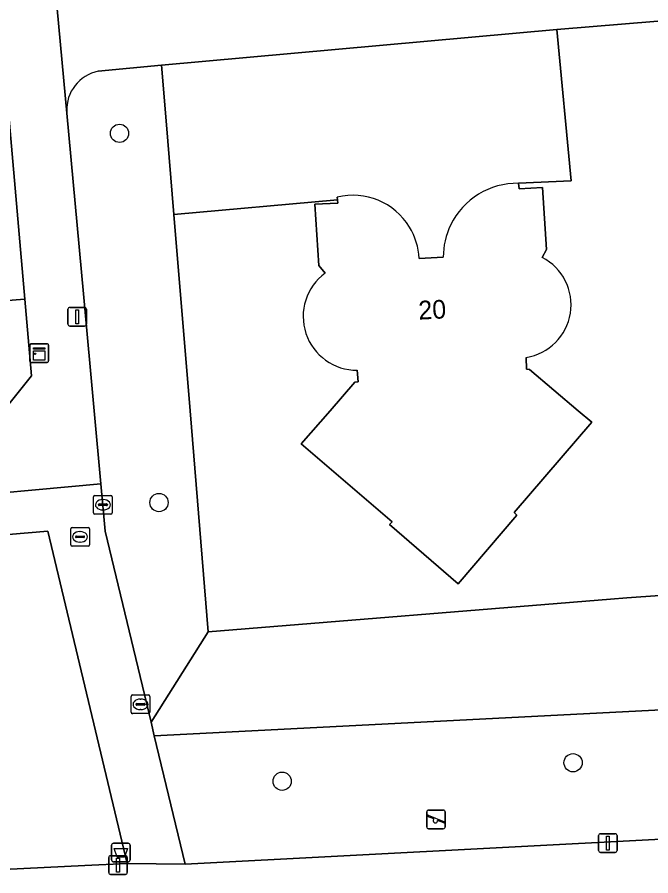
# Model space of a CAD drawing. Extents: x 160554 to 161248, y 385329 to 386506.
# Drawn here: x 161069.93 to 161103.88, y 385475.1 to 385521.08 of the extents above; entities that cross this region are included whole.
import ezdxf

# ---------------------------------------------------------------- set-up
doc = ezdxf.new("R2010")
doc.units = 0
for name, color, linetype in [('IMGEO_Afvalbak', 7, 'Continuous'), ('IMGEO_Boom', 7, 'Continuous'), ('IMGEO_Brandkraan', 7, 'Continuous'), ('IMGEO_Erf', 7, 'Continuous'), ('IMGEO_Groenvoorziening', 7, 'Continuous'), ('IMGEO_Hek', 7, 'Continuous'), ('IMGEO_Kast', 7, 'Continuous'), ('IMGEO_Kolk', 7, 'Continuous'), ('IMGEO_Lichtmast', 7, 'Continuous'), ('IMGEO_Pand', 7, 'Continuous'), ('IMGEO_Pand_nummerreeks', 7, 'Continuous'), ('IMGEO_Parkeervlak_open', 7, 'Continuous'), ('IMGEO_Rioolput', 7, 'Continuous'), ('IMGEO_Speelvoorziening', 7, 'Continuous'), ('IMGEO_Voetpad_open', 7, 'Continuous')]:
    doc.layers.add(name, color=color, linetype=linetype)

msp = doc.modelspace()

# ---------------------------------------------------------------- linework, layer by layer
at = {"layer": 'IMGEO_Afvalbak'}
for p, q in [((161075.09, 385476.846), (161075.88, 385476.846)), ((161075.88, 385476.846), (161075.09, 385476.846)), ((161074.99, 385475.946), (161074.99, 385476.746)), ((161074.99, 385476.746), (161074.99, 385475.946)), ((161075.98, 385476.746), (161075.98, 385475.946)), ((161075.98, 385475.946), (161075.98, 385476.746)), ((161075.88, 385475.846), (161075.09, 385475.846)), ((161075.09, 385475.846), (161075.88, 385475.846))]:
    msp.add_line(p, q, dxfattribs=at)
msp.add_lwpolyline([(161075.133, 385476.56), (161075.837, 385476.56), (161075.688, 385476.09), (161075.282, 385476.09), (161075.133, 385476.56)], dxfattribs=at)
for centre, start, end in [((161075.09, 385476.746), 90, 180), ((161075.09, 385476.746), 90, 180), ((161075.88, 385476.746), 0, 90), ((161075.88, 385476.746), 360, 90), ((161075.09, 385475.946), 180, 270), ((161075.09, 385475.946), 180, 270), ((161075.88, 385475.946), 270, 0), ((161075.88, 385475.946), 270, 0)]:
    msp.add_arc(centre, 0.1, start, end, dxfattribs=at)
at = {"layer": 'IMGEO_Boom'}
for centre in [(161075.416, 385514.863), (161077.531, 385495.089), (161099.716, 385481.154), (161084.129, 385480.164)]:
    msp.add_circle(centre, 0.489, dxfattribs=at)
at = {"layer": 'IMGEO_Brandkraan'}
for p, q in [((161072.802, 385492.826), (161072.802, 385493.678)), ((161072.877, 385493.752), (161073.729, 385493.752)), ((161073.29, 385493.532), (161073.315, 385493.532)), ((161073.803, 385493.678), (161073.803, 385492.826)), ((161073.061, 385493.246), (161073.061, 385493.258)), ((161073.499, 385493.209), (161073.101, 385493.209)), ((161073.104, 385493.295), (161073.502, 385493.295)), ((161073.313, 385492.972), (161073.288, 385492.972)), ((161073.545, 385493.258), (161073.545, 385493.246)), ((161073.729, 385492.752), (161072.877, 385492.752))]:
    msp.add_line(p, q, dxfattribs=at)
for points in [[(161072.802, 385492.826), (161072.802, 385493.678)], [(161072.877, 385493.752), (161073.729, 385493.752)], [(161073.803, 385493.678), (161073.803, 385492.826)], [(161073.729, 385492.752), (161072.877, 385492.752)]]:
    msp.add_lwpolyline(points, dxfattribs=at)
for centre, radius, start, end in [((161072.879, 385493.676), 0.0765, 91.552, 178.448), ((161072.879, 385493.676), 0.0765, 91.552, 178.448), ((161073.727, 385493.676), 0.0765, 1.552, 88.448), ((161073.727, 385493.676), 0.0765, 1.552, 88.448), ((161073.101, 385493.255), 0.0403, 85.8775, 175.7526), ((161073.098, 385493.245), 0.0366, 178.938, 274.7102), ((161073.502, 385493.252), 0.043, 264.8664, 352.4533), ((161073.506, 385493.257), 0.0386, 1.7309, 96.639), ((161072.879, 385492.828), 0.0765, 181.552, 268.448), ((161072.879, 385492.828), 0.0765, 181.552, 268.448), ((161073.727, 385492.828), 0.0765, 271.552, 358.448), ((161073.727, 385492.828), 0.0765, 271.552, 358.448)]:
    msp.add_arc(centre, radius, start, end, dxfattribs=at)
for centre, major_axis, ratio, start_param, end_param in [((161073.289, 385493.252), (-0.387, 0.002), 0.722429, 4.712389, 7.853982), ((161073.314, 385493.252), (-0.39, 0.002), 0.717154, 1.570796, 4.712389)]:
    msp.add_ellipse(centre, major_axis=major_axis, ratio=ratio, start_param=start_param, end_param=end_param, dxfattribs=at)
at = {"layer": 'IMGEO_Erf'}
for points in [[(161055.383, 385534.953), (161054.863, 385540.93), (161051.732, 385540.657), (161051.228, 385546.438), (161054.359, 385546.711), (161054.342, 385546.908), (161053.822, 385552.885), (161050.82, 385552.623), (161050.31, 385558.469), (161053.313, 385558.73), (161053.29, 385558.99), (161061.734, 385559.726), (161062.266, 385553.62), (161062.786, 385547.643), (161063.307, 385541.665), (161063.827, 385535.688), (161064.348, 385529.711), (161064.868, 385523.733), (161065.389, 385517.756), (161065.91, 385511.778), (161066.441, 385505.676), (161070.343, 385505.975), (161065.541, 385560.907)], [(161133.129, 385516.169), (161132.125, 385523.449), (161118.748, 385522.087), (161098.852, 385520.428), (161099.614, 385512.321), (161096.798, 385512.189), (161096.834, 385511.893), (161098.073, 385511.953), (161098.284, 385508.638), (161098.064, 385508.211)], [(161086.428, 385507.375), (161086.093, 385507.779), (161085.879, 385511.067), (161087.118, 385511.127), (161087.1, 385511.298), (161078.327, 385510.513), (161079.193, 385500), (161080.166, 385488.17), (161101.718, 385489.917), (161102.588, 385489.988), (161119.033, 385491.139)], [(161097.203, 385502.861), (161097.217, 385502.237), (161097.376, 385502.22), (161099.996, 385500), (161100.713, 385499.393), (161096.55, 385494.556), (161096.708, 385494.41), (161093.56, 385490.732), (161089.884, 385493.907), (161090.021, 385494.054), (161085.153, 385498.232), (161086.695, 385500), (161088.029, 385501.53), (161088.208, 385501.553), (161088.156, 385502.174)]]:
    msp.add_lwpolyline(points, dxfattribs=at)
for centre, radius, start, end in [((161096.753, 385505.678), 2.852, 279.0799, 62.6351), ((161088.135, 385505.054), 2.88, 126.3299, 270.4276)]:
    msp.add_arc(centre, radius, start, end, dxfattribs=at)
at = {"layer": 'IMGEO_Groenvoorziening'}
for points in [[(161077.669, 385518.505), (161074.274, 385518.185)], [(161077.913, 385515.539), (161077.669, 385518.505)], [(161072.592, 385516.029), (161072.598, 385515.941)], [(161072.598, 385515.941), (161073.484, 385506.275)], [(161078.327, 385510.513), (161077.913, 385515.539)], [(161080.166, 385488.17), (161079.193, 385500), (161078.327, 385510.513)], [(161073.484, 385506.275), (161074.057, 385500), (161074.414, 385496.088), (161074.646, 385493.548), (161077.103, 385483.331)], [(161077.103, 385483.331), (161080.166, 385488.17)]]:
    msp.add_lwpolyline(points, dxfattribs=at)
for points in [[(161065.454, 385495.276), (161069.208, 385500), (161070.701, 385501.878), (161070.343, 385505.975), (161066.441, 385505.676), (161057.997, 385504.94), (161051.262, 385504.235), (161048.883, 385504.024), (161049.237, 385500), (161049.778, 385493.86)], [(161059.018, 385474.939), (161073.558, 385475.649), (161075.831, 385475.76), (161071.572, 385493.562), (161069.469, 385493.374), (161059.526, 385492.486), (161044.759, 385491.168), (161004.362, 385487.56), (161000, 385487.24), (160999.764, 385487.223), (161000, 385486.307), (161000.493, 385484.392), (161001.192, 385481.774), (161013.981, 385484.729), (161021.904, 385472.987), (161034.076, 385473.696), (161039.256, 385473.975)], [(161137.199, 385485.658), (161136.266, 385492.761), (161119.071, 385491.304), (161119.033, 385491.139), (161102.588, 385489.988), (161101.718, 385489.917), (161080.166, 385488.17), (161077.103, 385483.331), (161077.279, 385482.601)], [(161138.095, 385478.829), (161137.199, 385485.658), (161077.279, 385482.601), (161078.932, 385475.726)]]:
    msp.add_lwpolyline(points, close=True, dxfattribs=at)
msp.add_arc((161074.688, 385516.128), 2.099, 101.3858, 182.6952, dxfattribs=at)
at = {"layer": 'IMGEO_Hek'}
for points in [[(161099.614, 385512.321), (161098.852, 385520.428)], [(161099.614, 385512.321), (161096.798, 385512.189)], [(161078.327, 385510.513), (161087.1, 385511.298)]]:
    msp.add_lwpolyline(points, dxfattribs=at)
at = {"layer": 'IMGEO_Kast'}
for p, q in [((161070.691, 385503.592), (161071.532, 385503.592)), ((161071.532, 385503.592), (161070.691, 385503.592)), ((161071.616, 385503.517), (161071.616, 385502.676)), ((161071.616, 385502.676), (161071.616, 385503.517)), ((161070.616, 385502.667), (161070.616, 385503.508)), ((161070.616, 385503.508), (161070.616, 385502.667)), ((161071.541, 385502.592), (161070.7, 385502.592)), ((161070.7, 385502.592), (161071.541, 385502.592))]:
    msp.add_line(p, q, dxfattribs=at)
for points in [[(161070.811, 385503.382), (161071.411, 385503.382), (161071.411, 385503.297), (161070.811, 385503.297), (161070.811, 385503.382)], [(161070.811, 385503.207), (161071.411, 385503.207), (161071.411, 385502.718), (161070.811, 385502.718), (161070.811, 385503.207)]]:
    msp.add_lwpolyline(points, dxfattribs=at)
msp.add_circle((161070.895, 385503.056), 0.0377, dxfattribs=at)
for centre, start, end in [((161070.694, 385503.514), 92.4484, 184.2845), ((161070.694, 385503.514), 92.4484, 184.2845), ((161071.538, 385503.514), 2.4484, 94.2845), ((161071.538, 385503.514), 2.4484, 94.2845), ((161070.694, 385502.67), 182.4484, 274.2845), ((161070.694, 385502.67), 182.4484, 274.2845), ((161071.538, 385502.67), 272.4484, 4.2845), ((161071.538, 385502.67), 272.4484, 4.2845)]:
    msp.add_arc(centre, 0.0779, start, end, dxfattribs=at)
at = {"layer": 'IMGEO_Kolk'}
for p, q in [((161074.025, 385494.545), (161074.025, 385495.397)), ((161074.1, 385495.471), (161074.952, 385495.471)), ((161074.513, 385495.251), (161074.538, 385495.251)), ((161075.026, 385495.397), (161075.026, 385494.545)), ((161074.284, 385494.965), (161074.284, 385494.977)), ((161074.722, 385494.928), (161074.324, 385494.928)), ((161074.327, 385495.014), (161074.725, 385495.014)), ((161074.768, 385494.977), (161074.768, 385494.965)), ((161074.952, 385494.471), (161074.1, 385494.471)), ((161074.536, 385494.691), (161074.511, 385494.691))]:
    msp.add_line(p, q, dxfattribs=at)
for points in [[(161074.025, 385494.545), (161074.025, 385495.397)], [(161074.1, 385495.471), (161074.952, 385495.471)], [(161075.026, 385495.397), (161075.026, 385494.545)], [(161074.952, 385494.471), (161074.1, 385494.471)]]:
    msp.add_lwpolyline(points, dxfattribs=at)
for centre, radius, start, end in [((161074.102, 385495.395), 0.0765, 91.552, 178.448), ((161074.102, 385495.395), 0.0765, 91.552, 178.448), ((161074.95, 385495.395), 0.0765, 1.552, 88.448), ((161074.95, 385495.395), 0.0765, 1.552, 88.448), ((161074.324, 385494.974), 0.0403, 85.8775, 175.7526), ((161074.321, 385494.964), 0.0366, 178.938, 274.7102), ((161074.725, 385494.971), 0.043, 264.8664, 352.4533), ((161074.729, 385494.976), 0.0386, 1.7309, 96.639), ((161074.102, 385494.547), 0.0765, 181.552, 268.448), ((161074.102, 385494.547), 0.0765, 181.552, 268.448), ((161074.95, 385494.547), 0.0765, 271.552, 358.448), ((161074.95, 385494.547), 0.0765, 271.552, 358.448)]:
    msp.add_arc(centre, radius, start, end, dxfattribs=at)
for centre, major_axis, ratio, start_param, end_param in [((161074.512, 385494.971), (-0.387, 0.002), 0.722429, 4.712389, 7.853982), ((161074.537, 385494.971), (-0.39, 0.002), 0.717154, 1.570796, 4.712389)]:
    msp.add_ellipse(centre, major_axis=major_axis, ratio=ratio, start_param=start_param, end_param=end_param, dxfattribs=at)
at = {"layer": 'IMGEO_Lichtmast'}
for p, q in [((161072.651, 385504.639), (161072.651, 385505.439)), ((161072.651, 385505.439), (161072.651, 385504.639)), ((161072.751, 385505.539), (161073.541, 385505.539)), ((161073.541, 385505.539), (161072.751, 385505.539)), ((161073.641, 385505.439), (161073.641, 385504.639)), ((161073.641, 385504.639), (161073.641, 385505.439)), ((161073.541, 385504.539), (161072.751, 385504.539)), ((161072.751, 385504.539), (161073.541, 385504.539)), ((161101.185, 385477.355), (161101.975, 385477.355)), ((161101.975, 385477.355), (161101.185, 385477.355)), ((161101.085, 385476.455), (161101.085, 385477.255)), ((161101.085, 385477.255), (161101.085, 385476.455)), ((161102.075, 385477.255), (161102.075, 385476.455)), ((161102.075, 385476.455), (161102.075, 385477.255)), ((161074.84, 385475.277), (161074.84, 385476.077)), ((161074.84, 385476.077), (161074.84, 385475.277)), ((161074.94, 385476.177), (161075.73, 385476.177)), ((161075.73, 385476.177), (161074.94, 385476.177)), ((161075.83, 385476.077), (161075.83, 385475.277)), ((161075.83, 385475.277), (161075.83, 385476.077)), ((161101.975, 385476.355), (161101.185, 385476.355)), ((161101.185, 385476.355), (161101.975, 385476.355)), ((161075.73, 385475.177), (161074.94, 385475.177)), ((161074.94, 385475.177), (161075.73, 385475.177))]:
    msp.add_line(p, q, dxfattribs=at)
for points in [[(161073.071, 385505.414), (161073.221, 385505.414), (161073.221, 385504.664), (161073.071, 385504.664), (161073.071, 385505.414)], [(161101.505, 385477.23), (161101.655, 385477.23), (161101.655, 385476.48), (161101.505, 385476.48), (161101.505, 385477.23)], [(161075.26, 385476.052), (161075.41, 385476.052), (161075.41, 385475.302), (161075.26, 385475.302), (161075.26, 385476.052)]]:
    msp.add_lwpolyline(points, dxfattribs=at)
for centre, start, end in [((161072.751, 385505.439), 90, 180), ((161072.751, 385505.439), 90, 180), ((161073.541, 385505.439), 0, 90), ((161073.541, 385505.439), 360, 90), ((161072.751, 385504.639), 180, 270), ((161072.751, 385504.639), 180, 270), ((161073.541, 385504.639), 270, 0), ((161073.541, 385504.639), 270, 0), ((161101.185, 385477.255), 90, 180), ((161101.185, 385477.255), 90, 180), ((161101.975, 385477.255), 0, 90), ((161101.975, 385477.255), 360, 90), ((161101.185, 385476.455), 180, 270), ((161101.185, 385476.455), 180, 270), ((161101.975, 385476.455), 270, 0), ((161101.975, 385476.455), 270, 0), ((161074.94, 385476.077), 90, 180), ((161074.94, 385476.077), 90, 180), ((161075.73, 385476.077), 0, 90), ((161075.73, 385476.077), 360, 90), ((161074.94, 385475.277), 180, 270), ((161074.94, 385475.277), 180, 270), ((161075.73, 385475.277), 270, 0), ((161075.73, 385475.277), 270, 0)]:
    msp.add_arc(centre, 0.1, start, end, dxfattribs=at)
at = {"layer": 'IMGEO_Pand'}
for points in [[(161098.064, 385508.211), (161098.284, 385508.638), (161098.073, 385511.953), (161096.834, 385511.893), (161096.798, 385512.189)], [(161087.084, 385511.451), (161087.1, 385511.298), (161087.118, 385511.127), (161085.879, 385511.067), (161086.093, 385507.779), (161086.428, 385507.375)], [(161092.759, 385508.231), (161091.469, 385508.168)], [(161088.156, 385502.174), (161088.208, 385501.553), (161088.029, 385501.53), (161086.695, 385500), (161085.153, 385498.232), (161090.021, 385494.054), (161089.884, 385493.907), (161093.56, 385490.732), (161096.708, 385494.41), (161096.55, 385494.556), (161100.713, 385499.393), (161099.996, 385500), (161097.376, 385502.22), (161097.217, 385502.237), (161097.203, 385502.861)]]:
    msp.add_lwpolyline(points, dxfattribs=at)
for centre, radius, start, end in [((161096.726, 385508.223), 3.967, 88.961, 154.1574), ((161087.912, 385507.987), 3.561, 31.4427, 103.4397), ((161096.744, 385508.218), 3.985, 154.2061, 179.8144), ((161087.929, 385507.991), 3.545, 2.8595, 31.5331), ((161096.753, 385505.678), 2.852, 279.0799, 62.6351), ((161088.135, 385505.054), 2.88, 126.3299, 270.4276)]:
    msp.add_arc(centre, radius, start, end, dxfattribs=at)
at = {"layer": 'IMGEO_Parkeervlak_open'}
for points in [[(161096.798, 385512.189), (161099.614, 385512.321), (161098.852, 385520.428), (161077.669, 385518.505), (161077.913, 385515.539), (161078.327, 385510.513), (161087.1, 385511.298), (161087.084, 385511.451)], [(161091.469, 385508.168), (161092.759, 385508.231)]]:
    msp.add_lwpolyline(points, dxfattribs=at)
for centre, radius, start, end in [((161096.726, 385508.223), 3.967, 88.961, 154.1574), ((161087.912, 385507.987), 3.561, 31.4427, 103.4397), ((161096.744, 385508.218), 3.985, 154.2061, 179.8144), ((161087.929, 385507.991), 3.545, 2.8595, 31.5331)]:
    msp.add_arc(centre, radius, start, end, dxfattribs=at)
at = {"layer": 'IMGEO_Rioolput'}
for p, q in [((161076.04, 385483.857), (161076.04, 385484.709)), ((161076.115, 385484.783), (161076.967, 385484.783)), ((161077.041, 385484.709), (161077.041, 385483.857)), ((161076.299, 385484.277), (161076.299, 385484.289)), ((161076.737, 385484.24), (161076.339, 385484.24)), ((161076.342, 385484.326), (161076.74, 385484.326)), ((161076.528, 385484.563), (161076.553, 385484.563)), ((161076.783, 385484.289), (161076.783, 385484.277)), ((161076.967, 385483.783), (161076.115, 385483.783)), ((161076.551, 385484.003), (161076.526, 385484.003))]:
    msp.add_line(p, q, dxfattribs=at)
for points in [[(161076.04, 385483.857), (161076.04, 385484.709)], [(161076.115, 385484.783), (161076.967, 385484.783)], [(161077.041, 385484.709), (161077.041, 385483.857)], [(161076.967, 385483.783), (161076.115, 385483.783)]]:
    msp.add_lwpolyline(points, dxfattribs=at)
for centre, radius, start, end in [((161076.117, 385484.707), 0.0765, 91.552, 178.448), ((161076.117, 385484.707), 0.0765, 91.552, 178.448), ((161076.965, 385484.707), 0.0765, 1.552, 88.448), ((161076.965, 385484.707), 0.0765, 1.552, 88.448), ((161076.339, 385484.286), 0.0403, 85.8775, 175.7526), ((161076.336, 385484.276), 0.0366, 178.938, 274.7102), ((161076.74, 385484.283), 0.043, 264.8664, 352.4533), ((161076.744, 385484.288), 0.0386, 1.7309, 96.639), ((161076.117, 385483.859), 0.0765, 181.552, 268.448), ((161076.117, 385483.859), 0.0765, 181.552, 268.448), ((161076.965, 385483.859), 0.0765, 271.552, 358.448), ((161076.965, 385483.859), 0.0765, 271.552, 358.448)]:
    msp.add_arc(centre, radius, start, end, dxfattribs=at)
for centre, major_axis, ratio, start_param, end_param in [((161076.527, 385484.283), (-0.387, 0.002), 0.722429, 4.712389, 7.853982), ((161076.552, 385484.283), (-0.39, 0.002), 0.717154, 1.570796, 4.712389)]:
    msp.add_ellipse(centre, major_axis=major_axis, ratio=ratio, start_param=start_param, end_param=end_param, dxfattribs=at)
at = {"layer": 'IMGEO_Speelvoorziening'}
for p, q in [((161091.874, 385477.717), (161091.874, 385478.517)), ((161091.874, 385478.517), (161091.874, 385477.717)), ((161092.257, 385478.145), (161091.918, 385478.282)), ((161091.943, 385478.342), (161092.819, 385477.989)), ((161091.974, 385478.617), (161092.764, 385478.617)), ((161092.764, 385478.617), (161091.974, 385478.617)), ((161092.864, 385478.517), (161092.864, 385477.717)), ((161092.864, 385477.717), (161092.864, 385478.517)), ((161092.795, 385477.929), (161092.455, 385478.066)), ((161092.764, 385477.617), (161091.974, 385477.617)), ((161091.974, 385477.617), (161092.764, 385477.617))]:
    msp.add_line(p, q, dxfattribs=at)
for centre, radius, start, end in [((161091.974, 385478.517), 0.1, 90, 180), ((161091.974, 385478.517), 0.1, 90, 180), ((161091.931, 385478.312), 0.0327, 68.078, 248.078), ((161092.764, 385478.517), 0.1, 0, 90), ((161092.764, 385478.517), 0.1, 360, 90), ((161092.336, 385478.055), 0.12, 130.9928, 5.1632), ((161092.807, 385477.959), 0.0327, 248.078, 68.078), ((161091.974, 385477.717), 0.1, 180, 270), ((161091.974, 385477.717), 0.1, 180, 270), ((161092.764, 385477.717), 0.1, 270, 0), ((161092.764, 385477.717), 0.1, 270, 0)]:
    msp.add_arc(centre, radius, start, end, dxfattribs=at)
at = {"layer": 'IMGEO_Voetpad_open'}
for points in [[(161060.535, 385617.772), (161062.796, 385592.405), (161062.932, 385590.876), (161064.786, 385570.078), (161064.802, 385570.012), (161065.542, 385560.933), (161065.541, 385560.907), (161070.343, 385505.975), (161070.701, 385501.878), (161069.208, 385500), (161065.454, 385495.276), (161074.414, 385496.088), (161074.057, 385500), (161073.484, 385506.275), (161072.598, 385515.941), (161071.555, 385527.133), (161071.554, 385527.151), (161071.552, 385527.169), (161064.234, 385611.073)], [(161071.555, 385527.133), (161072.598, 385515.941), (161072.592, 385516.029)], [(161074.274, 385518.185), (161077.669, 385518.505), (161098.852, 385520.428), (161118.748, 385522.087), (161132.125, 385523.449), (161129.051, 385526.24), (161123.108, 385525.73), (161121.73, 385525.612), (161102.391, 385523.95)], [(161069.469, 385493.374), (161071.572, 385493.562), (161075.831, 385475.76), (161078.932, 385475.726), (161077.279, 385482.601), (161077.103, 385483.331), (161074.646, 385493.548), (161074.414, 385496.088), (161065.454, 385495.276)], [(161069.71, 385472.482), (161076.464, 385472.863), (161079.665, 385472.955), (161100.981, 385474.144), (161102.66, 385474.238), (161107.462, 385474.476), (161108.778, 385474.498), (161113.496, 385474.74), (161113.516, 385474.343), (161116.241, 385474.444), (161116.23, 385474.815), (161120.845, 385475.019), (161125.695, 385475.233), (161125.713, 385474.836), (161128.193, 385474.937), (161128.172, 385475.343), (161132.97, 385475.555), (161138.499, 385475.796), (161138.095, 385478.829), (161078.932, 385475.726), (161075.831, 385475.76), (161073.558, 385475.649), (161059.018, 385474.939)]]:
    msp.add_lwpolyline(points, dxfattribs=at)
msp.add_arc((161074.688, 385516.128), 2.099, 101.3858, 182.6952, dxfattribs=at)

# ---------------------------------------------------------------- texts
at = {"layer": 'IMGEO_Pand_nummerreeks'}
msp.add_text('20', height=1, rotation=2.7959, dxfattribs=at).set_placement((161091.451, 385504.884))

doc.saveas('drawing.dxf')
